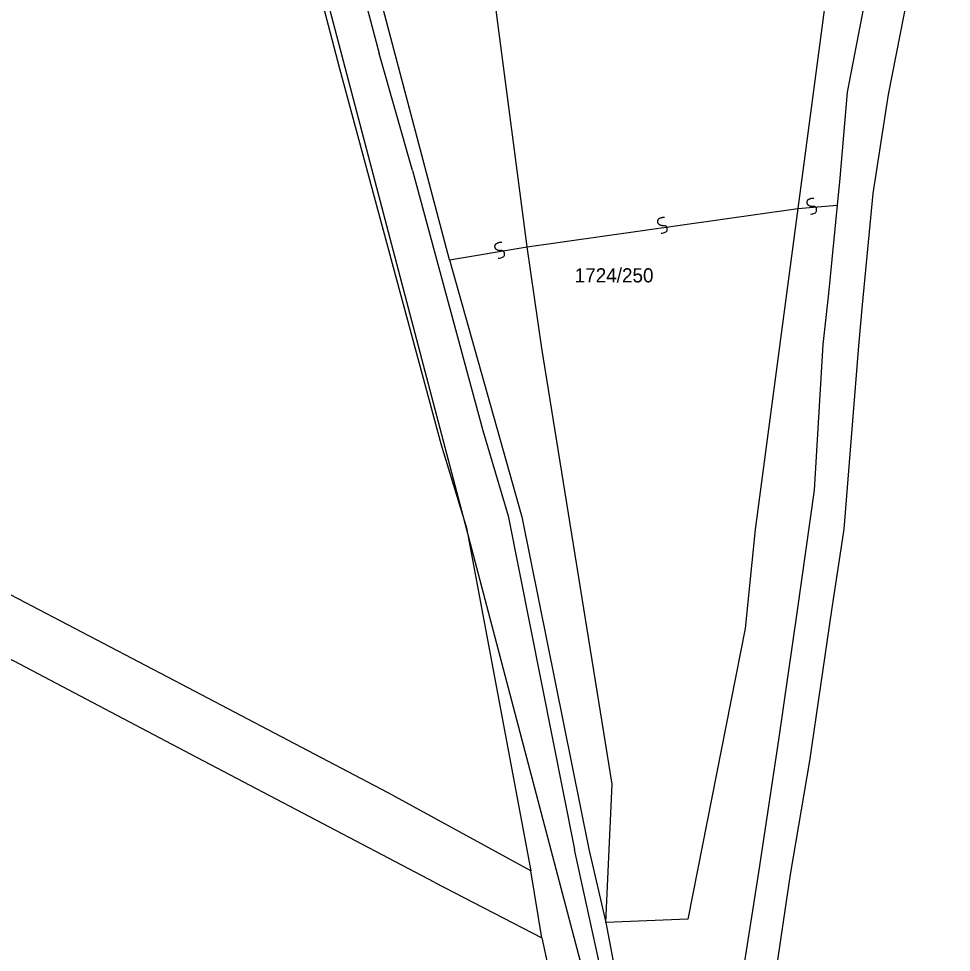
# Model space of a CAD drawing. Extents: x -581999 to -572728, y -1219553 to -1212032.
# Drawn here: x -578534.1 to -578402.1, y -1216070.7 to -1215938.4 of the extents above; entities that cross this region are included whole.
import ezdxf

# ---------------------------------------------------------------- set-up
doc = ezdxf.new("R2010")
doc.units = 0
for name, color, linetype in [('Vrstva 1', 7, 'Continuous'), ('Vrstva 2', 7, 'Continuous'), ('Vrstva 4', 7, 'Continuous'), ('Vrstva 6', 7, 'Continuous'), ('Vrstva 63', 7, 'Continuous')]:
    doc.layers.add(name, color=color, linetype=linetype)

msp = doc.modelspace()

# ---------------------------------------------------------------- linework, layer by layer
at = {"layer": 'Vrstva 1'}
for p, q in [((-578473.143, -1215972.573), (-578493.13, -1215897.217)), ((-578462.17, -1215970.735), (-578469.864, -1215912.223)), ((-578419.962, -1215935.749), (-578423.88, -1215965.335)), ((-578423.88, -1215965.335), (-578429.889, -1216010.794)), ((-578460.072, -1215985.099), (-578462.17, -1215970.735)), ((-578473.143, -1215972.573), (-578462.943, -1216009.001)), ((-578450.143, -1216046.854), (-578460.072, -1215985.099)), ((-578462.943, -1216009.001), (-578453.456, -1216056.034)), ((-578429.889, -1216010.794), (-578431.332, -1216024.799)), ((-578431.332, -1216024.799), (-578439.432, -1216065.969)), ((-578451.017, -1216066.447), (-578450.143, -1216046.854)), ((-578451.83, -1216072.7), (-578455.453, -1216056.08)), ((-578439.432, -1216065.969), (-578451.017, -1216066.447))]:
    msp.add_line(p, q, dxfattribs=at)
for points in [[(-578496.674, -1215892.126), (-578483.122, -1215943.385)], [(-578502.293, -1215893.67), (-578488.74, -1215945.511)], [(-578408.602, -1215909.469), (-578411.13, -1215919.853), (-578413.722, -1215932.401), (-578416.868, -1215948.84), (-578417.91, -1215961.024), (-578418.277, -1215964.854), (-578419.514, -1215977.339), (-578420.316, -1215984.568)], [(-578402.132, -1215909.667), (-578405.339, -1215918.442), (-578407.744, -1215932.103), (-578411.076, -1215949.161)], [(-578478.398, -1215959.925), (-578483.122, -1215943.385)], [(-578488.74, -1215945.511), (-578474.329, -1215998.782)], [(-578411.076, -1215949.161), (-578413.227, -1215963.196), (-578414.772, -1215978.954), (-578415.266, -1215984.762), (-578417.361, -1216010.718), (-578419.089, -1216022.206)], [(-578478.398, -1215959.925), (-578468.423, -1215996.752)], [(-578420.316, -1215984.568), (-578421.549, -1216005.213), (-578423.953, -1216022.261)], [(-578468.423, -1215996.752), (-578464.849, -1216008.818)], [(-578474.329, -1215998.782), (-578470.754, -1216010.556)], [(-578512.063, -1216032.197), (-578572.65, -1216000.474)], [(-578510.704, -1216042.101), (-578575.36, -1216008.048)], [(-578464.849, -1216008.818), (-578455.453, -1216056.08)], [(-578470.754, -1216010.556), (-578461.657, -1216059.131)], [(-578423.953, -1216022.261), (-578426.584, -1216040.546), (-578429.359, -1216059.01), (-578432.197, -1216077.046), (-578434.785, -1216094.886)], [(-578419.089, -1216022.206), (-578422.212, -1216043.517), (-578424.925, -1216059.633)], [(-578461.657, -1216059.131), (-578481.854, -1216048.064), (-578512.063, -1216032.197)], [(-578475.229, -1216060.748), (-578510.704, -1216042.101)], [(-578453.456, -1216056.034), (-578451.017, -1216066.447), (-578445.867, -1216093.905)], [(-578460.074, -1216068.613), (-578461.657, -1216059.131)], [(-578475.229, -1216060.748), (-578460.074, -1216068.613)], [(-578424.925, -1216059.633), (-578428.503, -1216083.533), (-578429.613, -1216091.929), (-578420.5, -1216094.532), (-578414.467, -1216095.958)], [(-578460.074, -1216068.613), (-578454.346, -1216095.173)]]:
    msp.add_lwpolyline(points, dxfattribs=at)
at = {"layer": 'Vrstva 4'}
for p, q in [((-578462.17, -1215970.735), (-578423.88, -1215965.335)), ((-578423.88, -1215965.335), (-578418.277, -1215964.854)), ((-578473.143, -1215972.573), (-578462.17, -1215970.735))]:
    msp.add_line(p, q, dxfattribs=at)
at = {"layer": 'Vrstva 6'}
for points in [[(-578422.077, -1215966.109), (-578421.226, -1215966.02), (-578421.174, -1215965.262), (-578421.49, -1215965.006), (-578421.906, -1215965.051), (-578422.238, -1215964.969), (-578422.455, -1215964.761), (-578422.546, -1215964.549), (-578422.547, -1215964.28), (-578422.344, -1215963.975), (-578421.756, -1215963.805), (-578421.576, -1215963.838)], [(-578443.219, -1215968.827), (-578442.368, -1215968.738), (-578442.316, -1215967.98), (-578442.632, -1215967.724), (-578443.048, -1215967.769), (-578443.38, -1215967.687), (-578443.597, -1215967.479), (-578443.688, -1215967.267), (-578443.689, -1215966.998), (-578443.486, -1215966.693), (-578442.898, -1215966.523), (-578442.718, -1215966.556)], [(-578466.259, -1215972.362), (-578465.408, -1215972.273), (-578465.356, -1215971.515), (-578465.672, -1215971.259), (-578466.088, -1215971.304), (-578466.42, -1215971.222), (-578466.637, -1215971.014), (-578466.728, -1215970.802), (-578466.729, -1215970.533), (-578466.526, -1215970.228), (-578465.938, -1215970.058), (-578465.758, -1215970.091)]]:
    msp.add_open_spline(points, degree=2, dxfattribs=at)
at = {"layer": 'Vrstva 63'}
for p, q in [((-578505.971, -1215876.912), (-578462.74, -1216041.281)), ((-578462.74, -1216041.281), (-578442.106, -1216119.73))]:
    msp.add_line(p, q, dxfattribs=at)

# ---------------------------------------------------------------- texts
at = {"layer": 'Vrstva 2'}
msp.add_text('1724/250', height=2, dxfattribs=at).set_placement((-578455.443, -1215975.777))

doc.saveas('drawing.dxf')
